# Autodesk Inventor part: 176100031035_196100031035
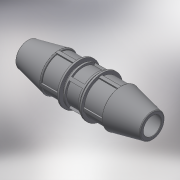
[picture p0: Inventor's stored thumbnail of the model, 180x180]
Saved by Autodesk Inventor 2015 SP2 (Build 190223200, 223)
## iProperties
Created: 2016-12
Part Number: 176100031035_196100031035
Material: Generic
Description: PLASSON UNIVERSAL SLIP REPAIR COUPLER 31-35 SERIES 17
Document SubType Name: Modeling
Designer: KIM
Mass: 305.707 g
Surface Area: 640.661 cm^2
Volume: 305.707 cm^3
Density: 1 g/cm^3
Appearance: Default
Author: KIM
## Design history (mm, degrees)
derived "17610.ipt"
feature "Solid1::17610.ipt"
tag "TaggingFeature1"
body "Solid1"
other parameters: "d5" = 143, "d11" = 35.75, "d12" = 2.86, "d13" = 49, "d14" = 52.5, "d15" = 35, "d16" = 34.3, "d17" = 60.8, "d20" = 64.6, "d21" = 80 deg, "d23" = 0, "d25" = 360 deg, "d31" = 28.6, "d32" = 68.4, "d33" = 80 deg, "d34" = 40 deg, "d35" = 60.8, "d36" = 11.44, "d37" = 0, "d39" = 360 deg, "d41" = 2.1, "d43" = 360 deg, "d48" = 1.75, "d52" = 0.76, "d55" = 76, "d56" = 69.92, "d_" = 35, "E_" = 76, "l_" = 143
